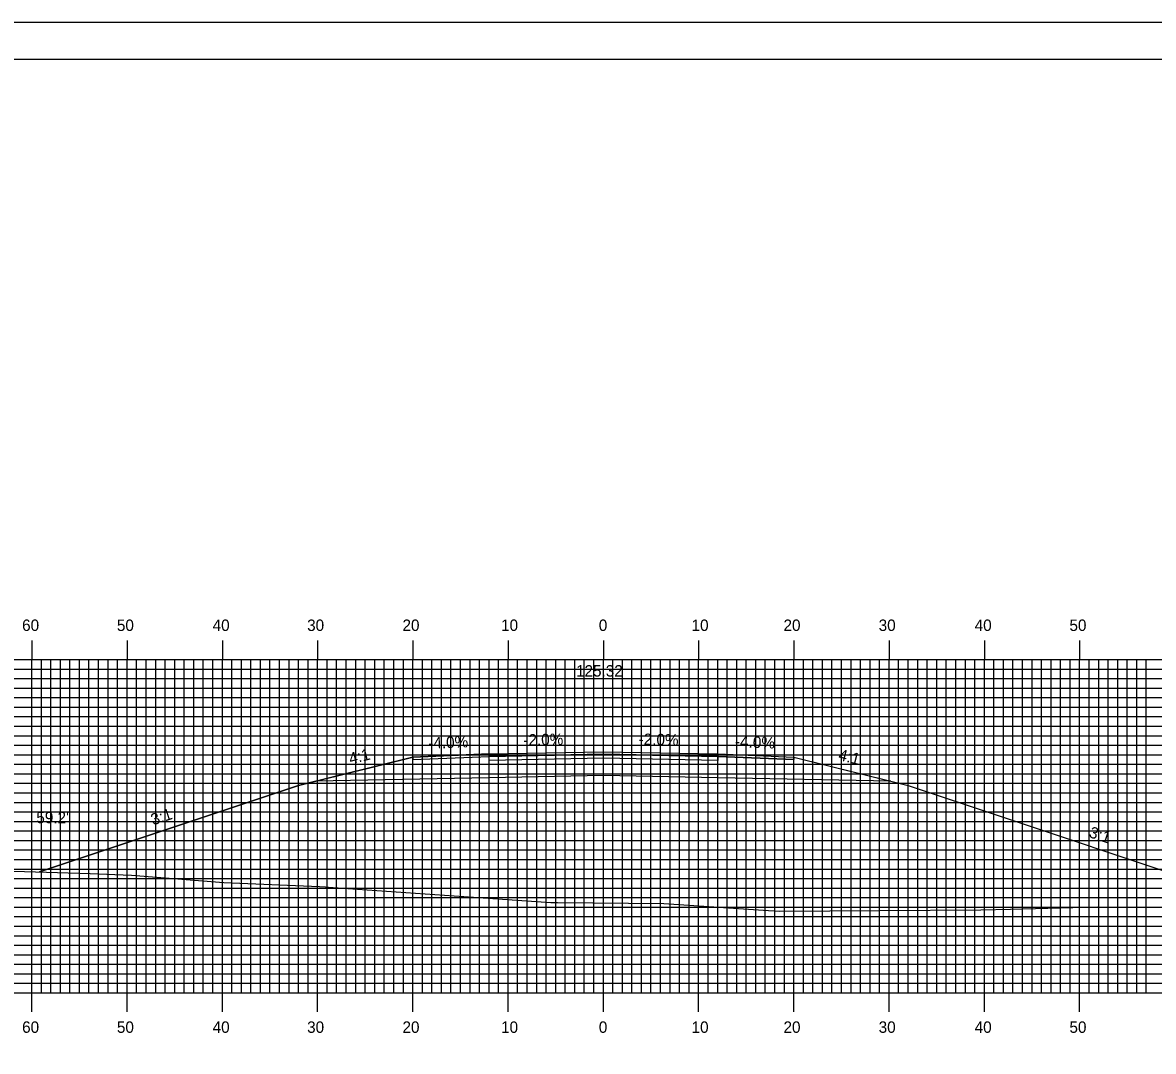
# Model space of a CAD drawing. Extents: x 1781073 to 1781416, y 442591 to 442811.
# Drawn here: x 1781177.9 to 1781296.6, y 442702.5 to 442810.5 of the extents above; entities that cross this region are included whole.
import ezdxf

# ---------------------------------------------------------------- set-up
doc = ezdxf.new("R2010")
doc.units = 0
for name, color, linetype in [('ANNOTATION', 7, 'Continuous'), ('BORDER', 7, 'Continuous'), ('D_Roadway_Centerline', 7, 'Continuous'), ('D_Roadway_Centerline_Text', 7, 'Continuous'), ('D_Roadway_Edge_Shoulder', 7, 'Continuous'), ('D_Roadway_Edge_TW', 7, 'Continuous'), ('D_Roadway_Pavement', 7, 'Continuous'), ('D_Roadway_SlopeLines', 7, 'Continuous'), ('D_Roadway_SubGrade', 7, 'Continuous'), ('D_Text_Standard', 7, 'Continuous'), ('H_V ANNOTATION', 7, 'Continuous'), ('MAJOR', 7, 'Continuous'), ('MINOR', 7, 'Continuous'), ('PLOT BOUNDARY', 7, 'Continuous'), ('S_Roadway_Centerline', 7, 'Continuous')]:
    doc.layers.add(name, color=color, linetype=linetype)

msp = doc.modelspace()

# ---------------------------------------------------------------- linework, layer by layer
at = {"layer": 'BORDER'}
msp.add_lwpolyline([(1781089.29, 442596.67), (1781409.29, 442596.67), (1781409.29, 442806.67), (1781089.29, 442806.67)], close=True, dxfattribs=at)
at = {"layer": 'D_Roadway_Centerline'}
msp.add_lwpolyline([(1781179.68, 442721.36), (1781206.89, 442730.43), (1781208.72, 442730.88), (1781218.89, 442733.43), (1781226.89, 442733.75), (1781238.89, 442733.99), (1781250.89, 442733.75), (1781258.89, 442733.43), (1781269.07, 442730.88), (1781270.89, 442730.43), (1781309.47, 442717.57)], dxfattribs=at)
at = {"layer": 'D_Roadway_Edge_Shoulder'}
for points in [[(1781226.89, 442733.75), (1781218.89, 442733.43), (1781218.89, 442733.18), (1781226.89, 442733.5)], [(1781250.89, 442733.75), (1781258.89, 442733.43), (1781258.89, 442733.18), (1781250.89, 442733.5)]]:
    msp.add_lwpolyline(points, close=True, dxfattribs=at)
at = {"layer": 'D_Roadway_Edge_TW'}
msp.add_lwpolyline([(1781226.89, 442733.5), (1781226.89, 442733.75), (1781238.89, 442733.99), (1781250.89, 442733.75), (1781250.89, 442733.5), (1781238.89, 442733.74)], close=True, dxfattribs=at)
at = {"layer": 'D_Roadway_Pavement'}
msp.add_lwpolyline([(1781226.89, 442733.08), (1781226.89, 442733.5), (1781238.89, 442733.74), (1781250.89, 442733.5), (1781250.89, 442733.08), (1781238.89, 442733.32)], close=True, dxfattribs=at)
at = {"layer": 'D_Roadway_SlopeLines'}
for points in [[(1781218.89, 442733.43), (1781206.89, 442730.43), (1781179.68, 442721.36)], [(1781258.89, 442733.43), (1781270.89, 442730.43), (1781309.47, 442717.57)]]:
    msp.add_lwpolyline(points, dxfattribs=at)
at = {"layer": 'D_Roadway_SubGrade'}
msp.add_lwpolyline([(1781226.89, 442731.25), (1781208.72, 442730.88), (1781218.89, 442733.43), (1781218.89, 442733.18), (1781226.89, 442733.5), (1781238.89, 442733.74), (1781250.89, 442733.5), (1781258.89, 442733.18), (1781258.89, 442733.43), (1781269.07, 442730.88), (1781250.89, 442731.25), (1781238.89, 442731.49)], close=True, dxfattribs=at)
at = {"layer": 'MAJOR'}
for p, q in [((1781178.89, 442745.67), (1781178.89, 442743.67)), ((1781188.89, 442745.67), (1781188.89, 442743.67)), ((1781198.89, 442745.67), (1781198.89, 442743.67)), ((1781208.89, 442745.67), (1781208.89, 442743.67)), ((1781218.89, 442745.67), (1781218.89, 442743.67)), ((1781228.89, 442745.67), (1781228.89, 442743.67)), ((1781238.89, 442745.67), (1781238.89, 442743.67)), ((1781248.89, 442745.67), (1781248.89, 442743.67)), ((1781258.89, 442745.67), (1781258.89, 442743.67)), ((1781268.89, 442745.67), (1781268.89, 442743.67)), ((1781278.89, 442745.67), (1781278.89, 442743.67)), ((1781288.89, 442745.67), (1781288.89, 442743.67)), ((1781098.89, 442743.67), (1781378.89, 442743.67)), ((1781098.89, 442743.67), (1781378.89, 442743.67)), ((1781178.89, 442708.67), (1781178.89, 442743.67)), ((1781188.89, 442708.67), (1781188.89, 442743.67)), ((1781198.89, 442708.67), (1781198.89, 442743.67)), ((1781208.89, 442708.67), (1781208.89, 442743.67)), ((1781218.89, 442708.67), (1781218.89, 442743.67)), ((1781228.89, 442708.67), (1781228.89, 442743.67)), ((1781238.89, 442708.67), (1781238.89, 442743.67)), ((1781248.89, 442708.67), (1781248.89, 442743.67)), ((1781258.89, 442708.67), (1781258.89, 442743.67)), ((1781268.89, 442708.67), (1781268.89, 442743.67)), ((1781278.89, 442708.67), (1781278.89, 442743.67)), ((1781288.89, 442708.67), (1781288.89, 442743.67)), ((1781098.89, 442738.67), (1781378.89, 442738.67)), ((1781098.89, 442733.67), (1781378.89, 442733.67)), ((1781098.89, 442728.67), (1781378.89, 442728.67)), ((1781098.89, 442723.67), (1781378.89, 442723.67)), ((1781098.89, 442718.67), (1781378.89, 442718.67)), ((1781098.89, 442713.67), (1781378.89, 442713.67)), ((1781098.89, 442708.67), (1781378.89, 442708.67)), ((1781098.89, 442708.67), (1781378.89, 442708.67)), ((1781178.89, 442706.66), (1781178.89, 442708.67)), ((1781188.89, 442706.66), (1781188.89, 442708.67)), ((1781198.89, 442706.66), (1781198.89, 442708.67)), ((1781208.89, 442706.66), (1781208.89, 442708.67)), ((1781218.89, 442706.66), (1781218.89, 442708.67)), ((1781228.89, 442706.66), (1781228.89, 442708.67)), ((1781238.89, 442706.66), (1781238.89, 442708.67)), ((1781248.89, 442706.66), (1781248.89, 442708.67)), ((1781258.89, 442706.66), (1781258.89, 442708.67)), ((1781268.89, 442706.66), (1781268.89, 442708.67)), ((1781278.89, 442706.66), (1781278.89, 442708.67)), ((1781288.89, 442706.66), (1781288.89, 442708.67))]:
    msp.add_line(p, q, dxfattribs=at)
at = {"layer": 'MINOR'}
for p, q in [((1781179.89, 442708.67), (1781179.89, 442743.67)), ((1781180.89, 442708.67), (1781180.89, 442743.67)), ((1781181.89, 442708.67), (1781181.89, 442743.67)), ((1781182.89, 442708.67), (1781182.89, 442743.67)), ((1781183.89, 442708.67), (1781183.89, 442743.67)), ((1781184.89, 442708.67), (1781184.89, 442743.67)), ((1781185.89, 442708.67), (1781185.89, 442743.67)), ((1781186.89, 442708.67), (1781186.89, 442743.67)), ((1781187.89, 442708.67), (1781187.89, 442743.67)), ((1781189.89, 442708.67), (1781189.89, 442743.67)), ((1781190.89, 442708.67), (1781190.89, 442743.67)), ((1781191.89, 442708.67), (1781191.89, 442743.67)), ((1781192.89, 442708.67), (1781192.89, 442743.67)), ((1781193.89, 442708.67), (1781193.89, 442743.67)), ((1781194.89, 442708.67), (1781194.89, 442743.67)), ((1781195.89, 442708.67), (1781195.89, 442743.67)), ((1781196.89, 442708.67), (1781196.89, 442743.67)), ((1781197.89, 442708.67), (1781197.89, 442743.67)), ((1781199.89, 442708.67), (1781199.89, 442743.67)), ((1781200.89, 442708.67), (1781200.89, 442743.67)), ((1781201.89, 442708.67), (1781201.89, 442743.67)), ((1781202.89, 442708.67), (1781202.89, 442743.67)), ((1781203.89, 442708.67), (1781203.89, 442743.67)), ((1781204.89, 442708.67), (1781204.89, 442743.67)), ((1781205.89, 442708.67), (1781205.89, 442743.67)), ((1781206.89, 442708.67), (1781206.89, 442743.67)), ((1781207.89, 442708.67), (1781207.89, 442743.67)), ((1781209.89, 442708.67), (1781209.89, 442743.67)), ((1781210.89, 442708.67), (1781210.89, 442743.67)), ((1781211.89, 442708.67), (1781211.89, 442743.67)), ((1781212.89, 442708.67), (1781212.89, 442743.67)), ((1781213.89, 442708.67), (1781213.89, 442743.67)), ((1781214.89, 442708.67), (1781214.89, 442743.67)), ((1781215.89, 442708.67), (1781215.89, 442743.67)), ((1781216.89, 442708.67), (1781216.89, 442743.67)), ((1781217.89, 442708.67), (1781217.89, 442743.67)), ((1781219.89, 442708.67), (1781219.89, 442743.67)), ((1781220.89, 442708.67), (1781220.89, 442743.67)), ((1781221.89, 442708.67), (1781221.89, 442743.67)), ((1781222.89, 442708.67), (1781222.89, 442743.67)), ((1781223.89, 442708.67), (1781223.89, 442743.67)), ((1781224.89, 442708.67), (1781224.89, 442743.67)), ((1781225.89, 442708.67), (1781225.89, 442743.67)), ((1781226.89, 442708.67), (1781226.89, 442743.67)), ((1781227.89, 442708.67), (1781227.89, 442743.67)), ((1781229.89, 442708.67), (1781229.89, 442743.67)), ((1781230.89, 442708.67), (1781230.89, 442743.67)), ((1781231.89, 442708.67), (1781231.89, 442743.67)), ((1781232.89, 442708.67), (1781232.89, 442743.67)), ((1781233.89, 442708.67), (1781233.89, 442743.67)), ((1781234.89, 442708.67), (1781234.89, 442743.67)), ((1781235.89, 442708.67), (1781235.89, 442743.67)), ((1781236.89, 442708.67), (1781236.89, 442743.67)), ((1781237.89, 442708.67), (1781237.89, 442743.67)), ((1781239.89, 442708.67), (1781239.89, 442743.67)), ((1781240.89, 442708.67), (1781240.89, 442743.67)), ((1781241.89, 442708.67), (1781241.89, 442743.67)), ((1781242.89, 442708.67), (1781242.89, 442743.67)), ((1781243.89, 442708.67), (1781243.89, 442743.67)), ((1781244.89, 442708.67), (1781244.89, 442743.67)), ((1781245.89, 442708.67), (1781245.89, 442743.67)), ((1781246.89, 442708.67), (1781246.89, 442743.67)), ((1781247.89, 442708.67), (1781247.89, 442743.67)), ((1781249.89, 442708.67), (1781249.89, 442743.67)), ((1781250.89, 442708.67), (1781250.89, 442743.67)), ((1781251.89, 442708.67), (1781251.89, 442743.67)), ((1781252.89, 442708.67), (1781252.89, 442743.67)), ((1781253.89, 442708.67), (1781253.89, 442743.67)), ((1781254.89, 442708.67), (1781254.89, 442743.67)), ((1781255.89, 442708.67), (1781255.89, 442743.67)), ((1781256.89, 442708.67), (1781256.89, 442743.67)), ((1781257.89, 442708.67), (1781257.89, 442743.67)), ((1781259.89, 442708.67), (1781259.89, 442743.67)), ((1781260.89, 442708.67), (1781260.89, 442743.67)), ((1781261.89, 442708.67), (1781261.89, 442743.67)), ((1781262.89, 442708.67), (1781262.89, 442743.67)), ((1781263.89, 442708.67), (1781263.89, 442743.67)), ((1781264.89, 442708.67), (1781264.89, 442743.67)), ((1781265.89, 442708.67), (1781265.89, 442743.67)), ((1781266.89, 442708.67), (1781266.89, 442743.67)), ((1781267.89, 442708.67), (1781267.89, 442743.67)), ((1781269.89, 442708.67), (1781269.89, 442743.67)), ((1781270.89, 442708.67), (1781270.89, 442743.67)), ((1781271.89, 442708.67), (1781271.89, 442743.67)), ((1781272.89, 442708.67), (1781272.89, 442743.67)), ((1781273.89, 442708.67), (1781273.89, 442743.67)), ((1781274.89, 442708.67), (1781274.89, 442743.67)), ((1781275.89, 442708.67), (1781275.89, 442743.67)), ((1781276.89, 442708.67), (1781276.89, 442743.67)), ((1781277.89, 442708.67), (1781277.89, 442743.67)), ((1781279.89, 442708.67), (1781279.89, 442743.67)), ((1781280.89, 442708.67), (1781280.89, 442743.67)), ((1781281.89, 442708.67), (1781281.89, 442743.67)), ((1781282.89, 442708.67), (1781282.89, 442743.67)), ((1781283.89, 442708.67), (1781283.89, 442743.67)), ((1781284.89, 442708.67), (1781284.89, 442743.67)), ((1781285.89, 442708.67), (1781285.89, 442743.67)), ((1781286.89, 442708.67), (1781286.89, 442743.67)), ((1781287.89, 442708.67), (1781287.89, 442743.67)), ((1781289.89, 442708.67), (1781289.89, 442743.67)), ((1781290.89, 442708.67), (1781290.89, 442743.67)), ((1781291.89, 442708.67), (1781291.89, 442743.67)), ((1781292.89, 442708.67), (1781292.89, 442743.67)), ((1781293.89, 442708.67), (1781293.89, 442743.67)), ((1781294.89, 442708.67), (1781294.89, 442743.67)), ((1781295.89, 442708.67), (1781295.89, 442743.67)), ((1781098.89, 442742.67), (1781378.89, 442742.67)), ((1781098.89, 442741.67), (1781378.89, 442741.67)), ((1781098.89, 442740.67), (1781378.89, 442740.67)), ((1781098.89, 442739.67), (1781378.89, 442739.67)), ((1781098.89, 442737.67), (1781378.89, 442737.67)), ((1781098.89, 442736.67), (1781378.89, 442736.67)), ((1781098.89, 442735.67), (1781378.89, 442735.67)), ((1781098.89, 442734.67), (1781378.89, 442734.67)), ((1781098.89, 442732.67), (1781378.89, 442732.67)), ((1781098.89, 442731.67), (1781378.89, 442731.67)), ((1781098.89, 442730.67), (1781378.89, 442730.67)), ((1781098.89, 442729.67), (1781378.89, 442729.67)), ((1781098.89, 442727.67), (1781378.89, 442727.67)), ((1781098.89, 442726.67), (1781378.89, 442726.67)), ((1781098.89, 442725.67), (1781378.89, 442725.67)), ((1781098.89, 442724.67), (1781378.89, 442724.67)), ((1781098.89, 442722.67), (1781378.89, 442722.67)), ((1781098.89, 442721.67), (1781378.89, 442721.67)), ((1781098.89, 442720.67), (1781378.89, 442720.67)), ((1781098.89, 442719.67), (1781378.89, 442719.67)), ((1781098.89, 442717.67), (1781378.89, 442717.67)), ((1781098.89, 442716.67), (1781378.89, 442716.67)), ((1781098.89, 442715.67), (1781378.89, 442715.67)), ((1781098.89, 442714.67), (1781378.89, 442714.67)), ((1781098.89, 442712.67), (1781378.89, 442712.67)), ((1781098.89, 442711.67), (1781378.89, 442711.67)), ((1781098.89, 442710.67), (1781378.89, 442710.67)), ((1781098.89, 442709.67), (1781378.89, 442709.67))]:
    msp.add_line(p, q, dxfattribs=at)
at = {"layer": 'PLOT BOUNDARY'}
msp.add_lwpolyline([(1781073.11, 442590.55), (1781413.11, 442590.55), (1781413.11, 442810.55), (1781073.11, 442810.55)], close=True, dxfattribs=at)
at = {"layer": 'S_Roadway_Centerline'}
msp.add_lwpolyline([(1781165.48, 442721.8), (1781185.02, 442721.19), (1781189.36, 442721.01), (1781199.06, 442720.25), (1781209.08, 442719.83), (1781209.73, 442719.8), (1781210.05, 442719.77), (1781233.37, 442718.16), (1781234.07, 442718.14), (1781245.23, 442718.05), (1781256.22, 442717.3), (1781257.42, 442717.25), (1781267.93, 442717.33), (1781278.53, 442717.39), (1781281.62, 442717.47), (1781290.8, 442717.69), (1781303.81, 442717.64)], dxfattribs=at)

# ---------------------------------------------------------------- texts
at = {"layer": 'ANNOTATION'}
for s, rotation, p in [('-2.0%', 1.1458, (1781230.5, 442734.62)), ('-2.0%', 358.8542, (1781242.58, 442734.71)), ('-4.0%', 2.2906, (1781220.53, 442734.29)), ('-4.0%', 357.7094, (1781252.69, 442734.48)), ('4:1', 14.0362, (1781212.34, 442732.65)), ('4:1', 345.9638, (1781263.49, 442733.14)), ('3:1', 18.4348, (1781191.62, 442726.25)), ('3:1', 341.5652, (1781289.79, 442725.04))]:
    msp.add_text(s, height=1.2, rotation=rotation, dxfattribs=at).set_placement(p)
at = {"layer": 'D_Roadway_Centerline'}
for s, p in [('C', (1781238.89, 442733.99)), ('L', (1781238.89, 442733.98))]:
    msp.add_text(s, height=0.0146, dxfattribs=at).set_placement(p)
at = {"layer": 'D_Roadway_Centerline_Text'}
msp.add_text('125.32', height=1.2, dxfattribs=at).set_placement((1781236.02, 442741.88))
at = {"layer": 'D_Text_Standard'}
msp.add_text("59.2'", height=1.2, dxfattribs=at).set_placement((1781179.36, 442726.48))
at = {"layer": 'H_V ANNOTATION'}
for s, p in [('60', (1781177.87, 442746.67)), ('50', (1781187.82, 442746.67)), ('40', (1781197.87, 442746.67)), ('30', (1781207.79, 442746.67)), ('20', (1781217.8, 442746.67)), ('10', (1781228.15, 442746.67)), ('0', (1781238.41, 442746.67)), ('10', (1781248.15, 442746.67)), ('20', (1781257.8, 442746.67)), ('30', (1781267.79, 442746.67)), ('40', (1781277.87, 442746.67)), ('50', (1781287.82, 442746.67)), ('60', (1781177.87, 442704.47)), ('50', (1781187.82, 442704.47)), ('40', (1781197.87, 442704.47)), ('30', (1781207.79, 442704.47)), ('20', (1781217.8, 442704.47)), ('10', (1781228.15, 442704.47)), ('0', (1781238.41, 442704.47)), ('10', (1781248.15, 442704.47)), ('20', (1781257.8, 442704.47)), ('30', (1781267.79, 442704.47)), ('40', (1781277.87, 442704.47)), ('50', (1781287.82, 442704.47))]:
    msp.add_text(s, height=1.2, dxfattribs=at).set_placement(p)

doc.saveas('drawing.dxf')
